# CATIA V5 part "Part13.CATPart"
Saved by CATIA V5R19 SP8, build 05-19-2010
Part number: Couronne
Bounding box of the stored display mesh (mm): x 0 to 60, y 724.08 to 1517.308, z -369.243 to 427.344
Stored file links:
  G:\EU_thinkMotion\CFAO_2010\MMS_groupe1\MMS_groupe1\OK\ppiault\piault\piault_cfao\Part13.CATPart
  D:\Catia\Finaltest.CATProduct
  G:\Catia Projet\CFAO2\Product2.CATProduct
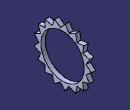
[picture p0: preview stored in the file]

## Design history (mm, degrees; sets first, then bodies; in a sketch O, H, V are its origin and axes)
Parameters
  rayon_int_couronne = 328 mm
  rayon_ext_couronne = 400 mm
  petit_rayon_couronne = 300 mm
External parameters (linked from other documents)
  External.DiametreRabatteur = 400 mm
Body1 (main body)
  Sketch1 on yz-plane, origin (0, 0, 0), H (0, 1, 0), V (0, 0, 1)
    circle A1 centre (1117.3078, 29.0696) radius 300
    point P1 (1117.3078, 29.0696)
    arc A2 centre (1117.3078, 29.0696) radius 328 from (1439.9132, 88.3125) to (1439.8515, -30.5086) ccw
    point P2 (1117.3078, 29.0696)
    line L1 (1439.9132, 88.3125) -> (1517.3077, 28.8617)
    point P4 (1517.3077, 28.8617)
    line L2 (1517.3077, 28.8617) -> (1439.8515, -30.5086)
    radius A2 = 328 {= External.DiametreRabatteur *0.82}
    radius A1 = 300 {= External.DiametreRabatteur -100mm}
    distance P4 P2 = 400 {= External.DiametreRabatteur}
    angle L1 L2 = 75
    coincidence: P1 P2
  Pad1: profile Sketch1, direction (1, 0, 0), length 60
  CircPattern1: of Pad1, instances 18, angular step 21.1765, axis from end face of Pad1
